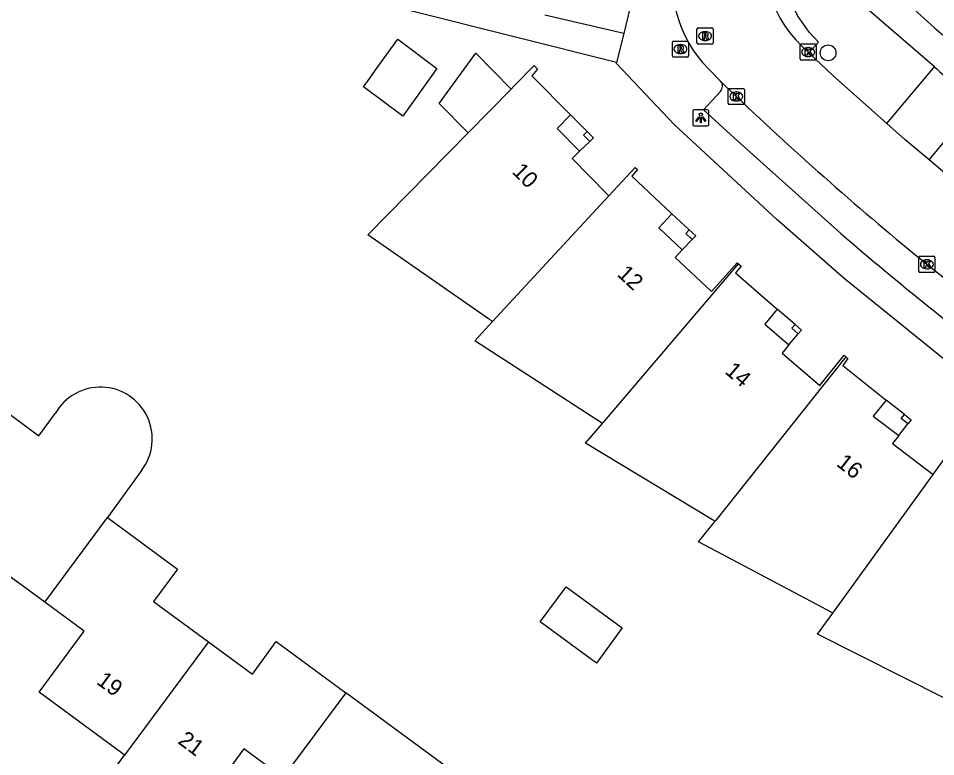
# Model space of a CAD drawing. Extents: x 163268 to 164360, y 381529 to 382285.
# Drawn here: x 163937.9 to 163994.8, y 382064.1 to 382109.9 of the extents above; entities that cross this region are included whole.
import ezdxf

# ---------------------------------------------------------------- set-up
doc = ezdxf.new("R2010")
doc.units = 0
for name, color, linetype in [('IMGEO_Boom', 7, 'Continuous'), ('IMGEO_Haag', 7, 'Continuous'), ('IMGEO_Kolk', 7, 'Continuous'), ('IMGEO_Lichtpunt', 7, 'Continuous'), ('IMGEO_Pand', 7, 'Continuous'), ('IMGEO_Pand_nummerreeks', 7, 'Continuous'), ('IMGEO_Pand_overbouw', 7, 'Continuous'), ('IMGEO_Rijbaan_lokaal_open', 7, 'Continuous'), ('IMGEO_Rioolput', 7, 'Continuous'), ('IMGEO_Voetpad_open', 7, 'Continuous')]:
    doc.layers.add(name, color=color, linetype=linetype)

msp = doc.modelspace()

# ---------------------------------------------------------------- linework, layer by layer
at = {"layer": 'IMGEO_Boom'}
msp.add_circle((163988.154, 382107.758), 0.489, dxfattribs=at)
at = {"layer": 'IMGEO_Haag'}
msp.add_lwpolyline([(163986.97, 382107.756), (163987.155, 382107.958), (163987.551, 382108.409), (163986.985, 382109.03), (163986.253, 382110.061), (163985.616, 382111.466), (163985.288, 382112.875), (163985.241, 382114.311), (163985.439, 382115.656), (163985.995, 382117.939), (163986.505, 382117.847)], dxfattribs=at)
at = {"layer": 'IMGEO_Kolk'}
for p, q in [((163986.42, 382107.379), (163986.42, 382108.231)), ((163986.495, 382108.305), (163987.347, 382108.305)), ((163986.908, 382108.085), (163986.933, 382108.085)), ((163987.421, 382108.231), (163987.421, 382107.379)), ((163987.347, 382107.305), (163986.495, 382107.305)), ((163986.931, 382107.525), (163986.906, 382107.525)), ((163981.96, 382104.629), (163981.96, 382105.481)), ((163982.035, 382105.555), (163982.887, 382105.555)), ((163982.448, 382105.335), (163982.473, 382105.335)), ((163982.961, 382105.481), (163982.961, 382104.629)), ((163982.887, 382104.555), (163982.035, 382104.555)), ((163982.471, 382104.775), (163982.446, 382104.775)), ((163993.78, 382094.227), (163993.78, 382095.079)), ((163993.855, 382095.153), (163994.707, 382095.153)), ((163994.268, 382094.933), (163994.293, 382094.933)), ((163994.781, 382095.079), (163994.781, 382094.227)), ((163994.291, 382094.373), (163994.266, 382094.373)), ((163994.707, 382094.153), (163993.855, 382094.153))]:
    msp.add_line(p, q, dxfattribs=at)
for points in [[(163986.42, 382107.379), (163986.42, 382108.231)], [(163986.495, 382108.305), (163987.347, 382108.305)], [(163986.741, 382108.005), (163986.864, 382108.005), (163986.864, 382107.854), (163986.994, 382108.005), (163987.158, 382108.005), (163987.012, 382107.854), (163987.165, 382107.605), (163987.013, 382107.605), (163986.928, 382107.769), (163986.864, 382107.702), (163986.864, 382107.605), (163986.741, 382107.605), (163986.741, 382108.005)], [(163987.421, 382108.231), (163987.421, 382107.379)], [(163987.347, 382107.305), (163986.495, 382107.305)], [(163981.96, 382104.629), (163981.96, 382105.481)], [(163982.035, 382105.555), (163982.887, 382105.555)], [(163982.281, 382105.255), (163982.404, 382105.255), (163982.404, 382105.104), (163982.534, 382105.255), (163982.698, 382105.255), (163982.552, 382105.104), (163982.705, 382104.855), (163982.553, 382104.855), (163982.468, 382105.019), (163982.404, 382104.952), (163982.404, 382104.855), (163982.281, 382104.855), (163982.281, 382105.255)], [(163982.961, 382105.481), (163982.961, 382104.629)], [(163982.887, 382104.555), (163982.035, 382104.555)], [(163993.78, 382094.227), (163993.78, 382095.079)], [(163993.855, 382095.153), (163994.707, 382095.153)], [(163994.101, 382094.853), (163994.224, 382094.853), (163994.224, 382094.702), (163994.354, 382094.853), (163994.518, 382094.853), (163994.372, 382094.702), (163994.525, 382094.453), (163994.373, 382094.453), (163994.288, 382094.617), (163994.224, 382094.55), (163994.224, 382094.453), (163994.101, 382094.453), (163994.101, 382094.853)], [(163994.781, 382095.079), (163994.781, 382094.227)], [(163994.707, 382094.153), (163993.855, 382094.153)]]:
    msp.add_lwpolyline(points, dxfattribs=at)
for centre, start, end in [((163986.497, 382108.229), 91.552, 178.448), ((163986.497, 382108.229), 91.552, 178.448), ((163987.345, 382108.229), 1.552, 88.448), ((163987.345, 382108.229), 1.552, 88.448), ((163986.497, 382107.381), 181.552, 268.448), ((163986.497, 382107.381), 181.552, 268.448), ((163987.345, 382107.381), 271.552, 358.448), ((163987.345, 382107.381), 271.552, 358.448), ((163982.037, 382105.479), 91.552, 178.448), ((163982.037, 382105.479), 91.552, 178.448), ((163982.885, 382105.479), 1.552, 88.448), ((163982.885, 382105.479), 1.552, 88.448), ((163982.037, 382104.631), 181.552, 268.448), ((163982.037, 382104.631), 181.552, 268.448), ((163982.885, 382104.631), 271.552, 358.448), ((163982.885, 382104.631), 271.552, 358.448), ((163993.857, 382095.077), 91.552, 178.448), ((163993.857, 382095.077), 91.552, 178.448), ((163994.705, 382095.077), 1.552, 88.448), ((163994.705, 382095.077), 1.552, 88.448), ((163993.857, 382094.229), 181.552, 268.448), ((163993.857, 382094.229), 181.552, 268.448), ((163994.705, 382094.229), 271.552, 358.448), ((163994.705, 382094.229), 271.552, 358.448)]:
    msp.add_arc(centre, 0.0765, start, end, dxfattribs=at)
for centre, major_axis, ratio, start_param, end_param in [((163986.907, 382107.805), (-0.387, 0.002), 0.722429, 4.712389, 7.853982), ((163986.932, 382107.805), (-0.39, 0.002), 0.717154, 1.570796, 4.712389), ((163982.447, 382105.055), (-0.387, 0.002), 0.722429, 4.712389, 7.853982), ((163982.472, 382105.055), (-0.39, 0.002), 0.717154, 1.570796, 4.712389), ((163994.267, 382094.653), (-0.387, 0.002), 0.722429, 4.712389, 7.853982), ((163994.292, 382094.653), (-0.39, 0.002), 0.717154, 1.570796, 4.712389)]:
    msp.add_ellipse(centre, major_axis=major_axis, ratio=ratio, start_param=start_param, end_param=end_param, dxfattribs=at)
at = {"layer": 'IMGEO_Lichtpunt'}
for p, q in [((163979.764, 382104.133), (163979.764, 382103.326)), ((163979.764, 382104.133), (163979.764, 382103.326)), ((163980.666, 382104.228), (163979.858, 382104.228)), ((163980.666, 382104.228), (163979.858, 382104.228)), ((163980.76, 382103.326), (163980.76, 382104.133)), ((163980.76, 382103.326), (163980.76, 382104.133)), ((163979.858, 382103.232), (163980.666, 382103.232)), ((163979.858, 382103.232), (163980.666, 382103.232))]:
    msp.add_line(p, q, dxfattribs=at)
for points in [[(163980.138, 382103.797), (163980.177, 382103.769), (163979.989, 382103.507), (163979.951, 382103.534), (163980.138, 382103.797)], [(163980.24, 382103.749), (163980.287, 382103.749), (163980.287, 382103.427), (163980.24, 382103.427), (163980.24, 382103.749)], [(163980.35, 382103.769), (163980.388, 382103.796), (163980.575, 382103.534), (163980.536, 382103.506), (163980.35, 382103.769)]]:
    msp.add_lwpolyline(points, dxfattribs=at)
msp.add_circle((163980.263, 382103.931), 0.0994, dxfattribs=at)
for centre, start, end in [((163979.858, 382104.133), 90, 180), ((163979.858, 382104.133), 90, 180), ((163980.666, 382104.133), 0, 90), ((163980.666, 382104.133), 0, 90), ((163979.858, 382103.326), 180, 270), ((163979.858, 382103.326), 180, 270), ((163980.666, 382103.326), 270, 0), ((163980.666, 382103.326), 270, 360)]:
    msp.add_arc(centre, 0.0946, start, end, dxfattribs=at)
at = {"layer": 'IMGEO_Pand'}
for points in [[(163959.353, 382105.66), (163959.588, 382105.986), (163960.076, 382106.666), (163961.472, 382108.607), (163963.903, 382106.777), (163961.783, 382103.831), (163959.353, 382105.66)], [(163965.84, 382102.81), (163964.046, 382104.621), (163966.306, 382107.73), (163968.5, 382105.516)], [(163968.5, 382105.516), (163968.674, 382105.693), (163969.936, 382106.964), (163970.144, 382106.746), (163969.785, 382106.331), (163972.185, 382103.908), (163971.347, 382103.078), (163972.748, 382101.665), (163972.28, 382101.201), (163974.455, 382099.006), (163974.568, 382098.892)], [(163965.84, 382102.81), (163968.5, 382105.516)], [(163967.35, 382091.103), (163967.096, 382091.28), (163959.626, 382096.487), (163965.84, 382102.81)], [(163972.996, 382102.655), (163973.222, 382102.877), (163973.601, 382102.491), (163973.375, 382102.269), (163972.996, 382102.655)], [(163974.568, 382098.892), (163976.198, 382100.651), (163976.342, 382100.522), (163975.988, 382100.109), (163978.469, 382097.779), (163977.662, 382096.919), (163979.113, 382095.557), (163978.662, 382095.076), (163980.915, 382092.961), (163982.52, 382094.754), (163982.598, 382094.685)], [(163967.35, 382091.103), (163974.568, 382098.892)], [(163979.549, 382096.786), (163979.946, 382096.416), (163979.727, 382096.184), (163979.33, 382096.554), (163979.549, 382096.786)], [(163974.159, 382084.799), (163982.598, 382094.685)], [(163982.598, 382094.685), (163982.757, 382094.544), (163982.419, 382094.126), (163984.986, 382091.879), (163984.224, 382090.954), (163985.721, 382089.657), (163985.304, 382089.154), (163987.645, 382087.149), (163989.145, 382089.022), (163989.264, 382088.923)], [(163974.159, 382084.799), (163973.81, 382085.024), (163966.245, 382089.911), (163967.35, 382091.103)], [(163986.107, 382090.933), (163986.513, 382090.58), (163986.305, 382090.339), (163985.899, 382090.692), (163986.107, 382090.933)], [(163989.264, 382088.923), (163981.142, 382078.732)], [(163989.264, 382088.923), (163989.385, 382088.822), (163989.06, 382088.391), (163991.75, 382086.229), (163990.955, 382085.242), (163992.538, 382084.044), (163992.14, 382083.542), (163994.665, 382081.632)], [(163935.007, 382082.087), (163937.434, 382085.352), (163939.214, 382084.029), (163940.235, 382085.404)], [(163992.883, 382085.34), (163993.295, 382085.006), (163993.106, 382084.765), (163992.694, 382085.099), (163992.883, 382085.34)], [(163981.142, 382078.732), (163980.982, 382078.828), (163973.107, 382083.567), (163974.159, 382084.799)], [(163994.665, 382081.632), (163996.036, 382083.522), (163996.245, 382083.363), (163995.935, 382082.978), (163998.709, 382080.879), (163997.945, 382079.853), (163999.581, 382078.716), (163999.197, 382078.168), (164000, 382077.614), (164001.668, 382076.463)], [(163945.582, 382081.87), (163943.468, 382078.969)], [(163988.438, 382073.046), (163994.665, 382081.632)], [(163939.586, 382073.719), (163943.468, 382078.969)], [(163943.468, 382078.969), (163947.816, 382075.772), (163946.335, 382073.759), (163949.743, 382071.253)], [(163988.438, 382073.046), (163987.8, 382073.385), (163980.126, 382077.457), (163981.142, 382078.732)], [(163939.586, 382073.719), (163937.199, 382075.482), (163934.423, 382071.7), (163933.569, 382072.332), (163932.843, 382071.346), (163933.062, 382071.185), (163932.868, 382070.92), (163928.887, 382073.852), (163929.802, 382075.084)], [(163971.908, 382074.676), (163975.391, 382072.129), (163973.792, 382069.943), (163970.309, 382072.49), (163971.908, 382074.676)], [(163944.536, 382064.238), (163944.416, 382064.327), (163939.241, 382068.14), (163942.017, 382071.922), (163939.586, 382073.719)], [(163995.878, 382067.516), (163995.407, 382067.753), (163987.493, 382071.743), (163988.438, 382073.046)], [(163949.743, 382071.253), (163944.536, 382064.238)], [(163949.743, 382071.253), (163952.458, 382069.257), (163953.94, 382071.271), (163958.25, 382068.102)], [(163958.25, 382068.102), (163954.343, 382062.856)], [(163965.972, 382062.412), (163958.25, 382068.102)], [(163954.343, 382062.856), (163951.934, 382064.636), (163949.158, 382060.854), (163948.304, 382061.486), (163947.578, 382060.5), (163947.797, 382060.339), (163947.603, 382060.074), (163943.622, 382063.006), (163944.536, 382064.238)]]:
    msp.add_lwpolyline(points, dxfattribs=at)
msp.add_arc((163943.038, 382083.833), 3.213, 322.3386, 150.7375, dxfattribs=at)
at = {"layer": 'IMGEO_Pand_overbouw'}
for points in [[(163973.222, 382102.877), (163972.185, 382103.908), (163971.347, 382103.078), (163972.748, 382101.665), (163973.375, 382102.269), (163972.996, 382102.655)], [(163979.727, 382096.184), (163979.33, 382096.554), (163979.549, 382096.786), (163978.469, 382097.779), (163977.662, 382096.919), (163979.113, 382095.557)], [(163986.107, 382090.933), (163984.986, 382091.879), (163984.224, 382090.954), (163985.721, 382089.657), (163986.305, 382090.339), (163985.899, 382090.692)], [(163993.106, 382084.765), (163992.694, 382085.099), (163992.883, 382085.34), (163991.75, 382086.229), (163990.955, 382085.242), (163992.538, 382084.044)]]:
    msp.add_lwpolyline(points, close=True, dxfattribs=at)
at = {"layer": 'IMGEO_Rijbaan_lokaal_open'}
for points in [[(163986.97, 382107.756), (163988.43, 382106.383), (163991.796, 382103.385)], [(163980.711, 382106.796), (163981.416, 382106.072), (163981.491, 382105.999)], [(163981.491, 382105.999), (163982.462, 382105.055)], [(163994.414, 382101.119), (163992.93, 382102.375), (163991.796, 382103.385)], [(164000, 382096.512), (163996.892, 382099.023), (163994.414, 382101.119)], [(163994.281, 382094.653), (164000, 382090.111)]]:
    msp.add_lwpolyline(points, dxfattribs=at)
for centre, radius, start, end in [((163992.27, 382113.998), 8.188, 166.4936, 229.6665), ((163986.231, 382112.23), 7.746, 166.5265, 224.5535), ((164125.577, 382255.75), 207.825, 226.47788, 230.81957)]:
    msp.add_arc(centre, radius, start, end, dxfattribs=at)
at = {"layer": 'IMGEO_Rioolput'}
for p, q in [((163980.025, 382108.372), (163980.025, 382109.224)), ((163980.1, 382109.298), (163980.952, 382109.298)), ((163980.513, 382109.078), (163980.538, 382109.078)), ((163981.026, 382109.224), (163981.026, 382108.372)), ((163978.574, 382108.489), (163979.426, 382108.489)), ((163980.536, 382108.518), (163980.511, 382108.518)), ((163978.499, 382107.563), (163978.499, 382108.415)), ((163978.987, 382108.269), (163979.012, 382108.269)), ((163979.5, 382108.415), (163979.5, 382107.563)), ((163980.952, 382108.298), (163980.1, 382108.298)), ((163979.426, 382107.489), (163978.574, 382107.489)), ((163979.01, 382107.709), (163978.985, 382107.709))]:
    msp.add_line(p, q, dxfattribs=at)
for points in [[(163980.025, 382108.372), (163980.025, 382109.224)], [(163980.1, 382109.298), (163980.952, 382109.298)], [(163980.614, 382108.996), (163980.362, 382108.998), (163980.362, 382108.598)], [(163981.026, 382109.224), (163981.026, 382108.372)], [(163978.574, 382108.489), (163979.426, 382108.489)], [(163980.362, 382108.598), (163980.486, 382108.598), (163980.486, 382108.76), (163980.497, 382108.76)], [(163980.54, 382108.917), (163980.486, 382108.917), (163980.486, 382108.836)], [(163980.486, 382108.836), (163980.538, 382108.836)], [(163980.544, 382108.731), (163980.615, 382108.598), (163980.755, 382108.598), (163980.69, 382108.724)], [(163978.499, 382107.563), (163978.499, 382108.415)], [(163979.088, 382108.187), (163978.836, 382108.189), (163978.836, 382107.789)], [(163978.836, 382107.789), (163978.96, 382107.789), (163978.96, 382107.951), (163978.971, 382107.951)], [(163979.014, 382108.108), (163978.96, 382108.108), (163978.96, 382108.027)], [(163978.96, 382108.027), (163979.012, 382108.027)], [(163979.018, 382107.922), (163979.089, 382107.789), (163979.229, 382107.789), (163979.164, 382107.915)], [(163979.5, 382108.415), (163979.5, 382107.563)], [(163980.952, 382108.298), (163980.1, 382108.298)], [(163979.426, 382107.489), (163978.574, 382107.489)]]:
    msp.add_lwpolyline(points, dxfattribs=at)
for centre, radius, start, end in [((163980.102, 382109.222), 0.0765, 91.552, 178.448), ((163980.102, 382109.222), 0.0765, 91.552, 178.448), ((163980.613, 382108.886), 0.109, 350.3612, 89.416), ((163980.95, 382109.222), 0.0765, 1.552, 88.448), ((163980.95, 382109.222), 0.0765, 1.552, 88.448), ((163978.576, 382108.413), 0.0765, 91.552, 178.448), ((163978.576, 382108.413), 0.0765, 91.552, 178.448), ((163979.424, 382108.413), 0.0765, 1.552, 88.448), ((163979.424, 382108.413), 0.0765, 1.552, 88.448), ((163980.496, 382108.707), 0.0533, 26.0293, 88.6989), ((163980.522, 382109.025), 0.19, 274.7715, 282.9687), ((163980.546, 382108.821), 0.0964, 77.0061, 93.1865), ((163980.56, 382108.878), 0.0378, 276.6634, 79.6772), ((163980.611, 382108.886), 0.112, 277.5842, 350.9817), ((163980.595, 382108.671), 0.108, 29.5134, 73.7905), ((163978.97, 382107.898), 0.0533, 26.0293, 88.6989), ((163978.996, 382108.216), 0.19, 274.7715, 282.9687), ((163979.02, 382108.012), 0.0964, 77.0061, 93.1865), ((163979.034, 382108.069), 0.0378, 276.6634, 79.6772), ((163979.087, 382108.077), 0.109, 350.3612, 89.416), ((163979.085, 382108.077), 0.112, 277.5842, 350.9817), ((163979.069, 382107.862), 0.108, 29.5134, 73.7905), ((163980.102, 382108.374), 0.0765, 181.552, 268.448), ((163980.102, 382108.374), 0.0765, 181.552, 268.448), ((163980.95, 382108.374), 0.0765, 271.552, 358.448), ((163980.95, 382108.374), 0.0765, 271.552, 358.448), ((163978.576, 382107.565), 0.0765, 181.552, 268.448), ((163978.576, 382107.565), 0.0765, 181.552, 268.448), ((163979.424, 382107.565), 0.0765, 271.552, 358.448), ((163979.424, 382107.565), 0.0765, 271.552, 358.448)]:
    msp.add_arc(centre, radius, start, end, dxfattribs=at)
for centre, major_axis, ratio, start_param, end_param in [((163980.512, 382108.798), (-0.387, 0.002), 0.722429, 4.712389, 7.853982), ((163980.537, 382108.798), (-0.39, 0.002), 0.717154, 1.570796, 4.712389), ((163978.986, 382107.989), (-0.387, 0.002), 0.722429, 4.712389, 7.853982), ((163979.011, 382107.989), (-0.39, 0.002), 0.717154, 1.570796, 4.712389)]:
    msp.add_ellipse(centre, major_axis=major_axis, ratio=ratio, start_param=start_param, end_param=end_param, dxfattribs=at)
at = {"layer": 'IMGEO_Voetpad_open'}
for points in [[(163975.044, 382107.165), (163917.66, 382121.564), (163917.983, 382122.991), (163919.277, 382122.698), (163919.741, 382122.581)], [(163977.832, 382118.691), (163975.495, 382108.964)], [(163994.746, 382106.886), (163988.042, 382112.698)], [(163975.495, 382108.964), (163970.597, 382110.099)], [(163975.495, 382108.964), (163975.044, 382107.165)], [(164040.069, 382061.177), (164037.434, 382062.442), (164026.92, 382067.895), (164019.118, 382072.286), (164011.629, 382077.008), (164003.484, 382082.618), (164000, 382085.233), (163996.064, 382088.188), (163989.156, 382093.775), (163984.98, 382097.44), (163978.602, 382103.308), (163975.025, 382107.091), (163975.044, 382107.165)], [(163991.796, 382103.385), (163994.746, 382106.886)], [(163988.942, 382096.557), (163982.334, 382102.485), (163980.429, 382104.232), (163981.475, 382105.352)], [(163994.414, 382101.119), (163997.347, 382104.631)]]:
    msp.add_lwpolyline(points, dxfattribs=at)
for centre, radius, start, end in [((164136.999, 382268.569), 213.532, 227.61476, 230.06764), ((164128.082, 382258.053), 201.569, 228.5863, 229.56481), ((163981.111, 382105.685), 0.493, 317.5721, 39.5947), ((164140.647, 382273.644), 233.183, 229.41419, 232.90315)]:
    msp.add_arc(centre, radius, start, end, dxfattribs=at)

# ---------------------------------------------------------------- texts
at = {"layer": 'IMGEO_Pand_nummerreeks'}
for s, rotation, p in [('10', 314.7363, (163968.508, 382100.347)), ('12', 316.9365, (163975.021, 382093.98)), ('14', 319.2341, (163981.7, 382087.944)), ('16', 321.8811, (163988.613, 382082.212)), ('19', 323.6172, (163942.732, 382068.698)), ('21', 323.4969, (163947.782, 382065.008))]:
    msp.add_text(s, height=1, rotation=rotation, dxfattribs=at).set_placement(p)

doc.saveas('drawing.dxf')
